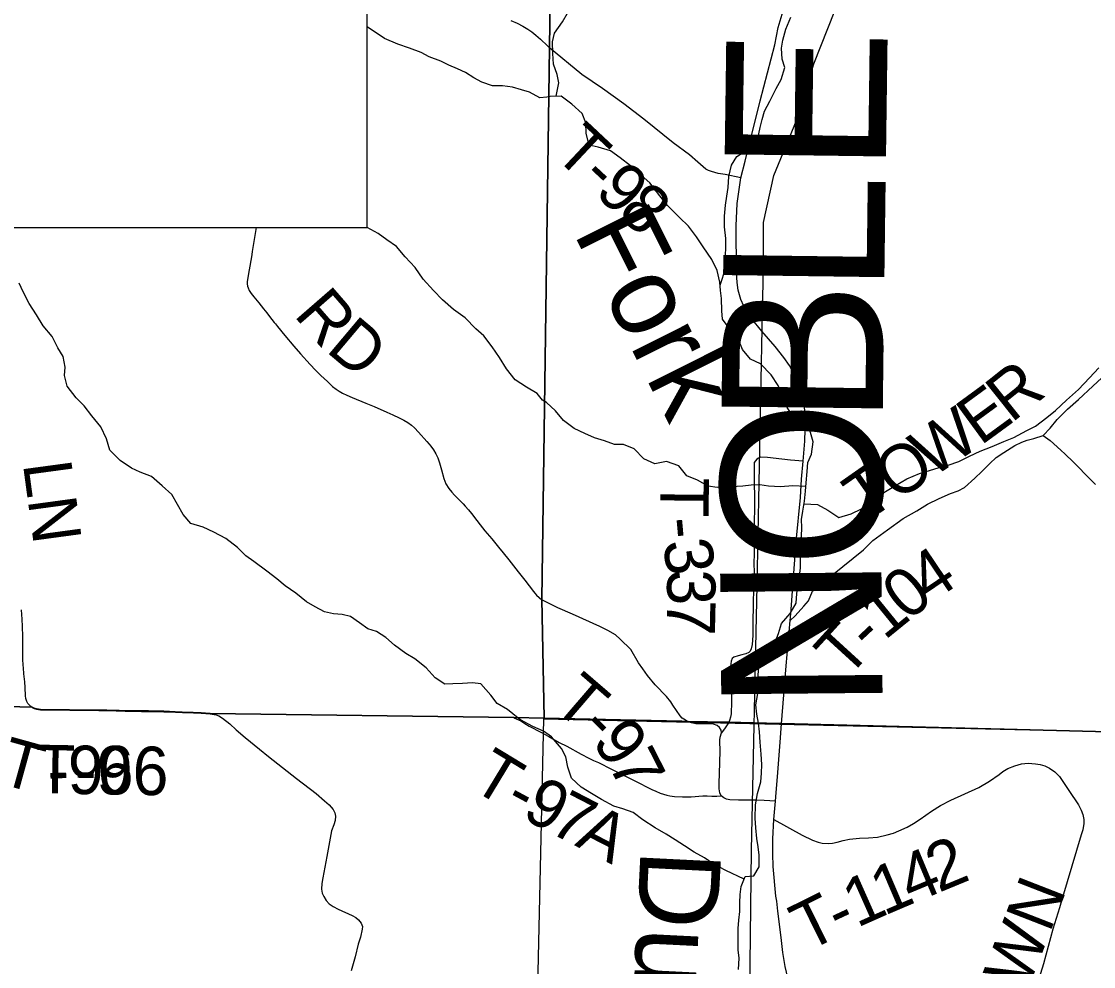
# Model space of a CAD drawing. Extents: x 0 to 34, y 0 to 22.
# Drawn here: x 4.145 to 5.404, y 15.796 to 16.906 of the extents above; entities that cross this region are included whole.
import ezdxf

# ---------------------------------------------------------------- set-up
doc = ezdxf.new("R2010")
doc.units = 0
for name, color, linetype in [('GM_X_Corporation', 7, 'Continuous'), ('GM_X_County_Road', 7, 'Continuous'), ('GM_X_County_Text', 7, 'Continuous'), ('GM_X_Minor_River', 7, 'Continuous'), ('GM_X_Minor_River_Text', 7, 'Continuous'), ('GM_X_Rail_Line', 7, 'Continuous'), ('GM_X_State_Route', 7, 'Continuous'), ('GM_X_Township_Road', 7, 'Continuous'), ('GM_X_Township_Road_Text', 7, 'Continuous'), ('SH_Data', 7, 'Continuous')]:
    doc.layers.add(name, color=color, linetype=linetype)

msp = doc.modelspace()

# ---------------------------------------------------------------- linework, layer by layer
at = {"layer": 'GM_X_Corporation'}
for points in [[(4.7905, 18.3604), (4.7823, 18.128), (4.7806, 18.0273), (4.765, 16.8754), (4.756, 16.2274), (4.759, 16.0879), (4.9206, 16.0842), (4.928, 16.0841), (4.9731, 16.0831), (4.975, 16.083), (5.0347, 16.0817), (5.0373, 16.0816), (6.4668, 16.045), (6.4721, 16.0449), (6.6873, 16.0404), (6.6909, 16.0403), (6.7034, 16.04), (6.9699, 16.0345), (6.9736, 16.0344), (7.8043, 16.0135), (7.8077, 16.0135), (8.4311, 16.0029), (8.4311, 20.028)], [(3.7652, 16.1115), (4.1576, 16.1007), (4.1598, 16.0996), (4.1627, 16.0987), (4.1674, 16.0981), (4.2356, 16.0972), (4.2455, 16.0972), (4.2746, 16.0965), (4.2814, 16.0964), (4.2857, 16.0964), (4.2943, 16.0963), (4.3121, 16.0959), (4.3257, 16.0953), (4.3338, 16.0949), (4.3467, 16.0944), (4.3559, 16.0941), (4.3665, 16.0934), (4.723, 16.0888), (4.759, 16.0879), (4.756, 16.2274), (4.765, 16.8754), (4.7806, 18.0273), (4.7823, 18.128), (4.7905, 18.3604)], [(4.7905, 18.3604), (4.7823, 18.128), (4.7806, 18.0273), (4.765, 16.8754), (4.756, 16.2274), (4.759, 16.0879), (4.723, 16.0888), (4.3665, 16.0934), (4.3559, 16.0941), (4.3467, 16.0944), (4.3338, 16.0949), (4.3257, 16.0953), (4.3121, 16.0959), (4.2943, 16.0963), (4.2857, 16.0964), (4.2814, 16.0964), (4.2746, 16.0965), (4.2455, 16.0972), (4.2356, 16.0972), (4.1674, 16.0981), (4.1627, 16.0987), (4.1598, 16.0996), (4.1576, 16.1007), (3.7652, 16.1115)], [(3.7652, 16.1115), (4.1576, 16.1007), (4.1598, 16.0996), (4.1627, 16.0987), (4.1674, 16.0981), (4.2356, 16.0972), (4.2455, 16.0972), (4.2746, 16.0965), (4.2814, 16.0964), (4.2857, 16.0964), (4.2943, 16.0963), (4.3121, 16.0959), (4.3257, 16.0953), (4.3338, 16.0949), (4.3467, 16.0944), (4.3559, 16.0941), (4.3665, 16.0934), (4.723, 16.0888), (4.759, 16.0879), (4.756, 16.2274), (4.765, 16.8754), (4.7806, 18.0273), (4.7823, 18.128), (4.0508, 18.1454)], [(6.4668, 16.045), (5.0373, 16.0816), (5.0347, 16.0817), (4.975, 16.083), (4.9731, 16.0831), (4.928, 16.0841), (4.9206, 16.0842), (4.759, 16.0879), (4.723, 16.0888), (4.3665, 16.0934), (4.3559, 16.0941), (4.3467, 16.0944), (4.3338, 16.0949), (4.3257, 16.0953), (4.3121, 16.0959), (4.2943, 16.0963), (4.2857, 16.0964), (4.2814, 16.0964), (4.2746, 16.0965), (4.2455, 16.0972), (4.2356, 16.0972), (4.1674, 16.0981), (4.1627, 16.0987), (4.1598, 16.0996), (4.1576, 16.1007), (3.7652, 16.1115)]]:
    msp.add_lwpolyline(points, dxfattribs=at)
msp.add_lwpolyline([(4.7583, 16.0869), (5.7783, 16.0638), (5.82, 16.0635), (5.7937, 15.0184), (4.7356, 15.0283), (4.7361, 15.0901)], close=True, dxfattribs=at)
at = {"layer": 'GM_X_County_Road'}
msp.add_lwpolyline([(4.7198, 16.9071), (4.7271, 16.9036), (4.7337, 16.9002), (4.7396, 16.8967), (4.7442, 16.8936), (4.7491, 16.8898), (4.7546, 16.8848), (4.7627, 16.8771), (4.7652, 16.8748)], dxfattribs=at)
at = {"layer": 'GM_X_Minor_River'}
for points in [[(4.7729, 16.8179), (4.7759, 16.8338), (4.774, 16.8437), (4.7698, 16.8558), (4.769, 16.8683), (4.7686, 16.8819), (4.7708, 16.8922), (4.7802, 16.9055), (4.7863, 16.9157)], [(4.9655, 16.5961), (4.9723, 16.6165), (4.9719, 16.6305), (4.9722, 16.6408), (4.9722, 16.651), (4.9706, 16.6647), (4.9706, 16.6772), (4.9717, 16.6901), (4.9732, 16.7007), (4.975, 16.7109), (4.9758, 16.7238), (4.9788, 16.7371), (4.9852, 16.7473), (4.9991, 16.7561), (5.0097, 16.7683), (5.0123, 16.7812), (5.0149, 16.7907), (5.0176, 16.8005), (5.0236, 16.8123), (5.0311, 16.8271), (5.0371, 16.8377), (5.0413, 16.8518), (5.0382, 16.8616), (5.0374, 16.8745), (5.0389, 16.884), (5.0427, 16.8969), (5.0483, 16.9109)], [(4.7621, 16.8168), (4.7538, 16.816), (4.7416, 16.8228), (4.7321, 16.8257), (4.7215, 16.8287), (4.7097, 16.8301), (4.698, 16.8304), (4.6858, 16.8344), (4.6763, 16.8397), (4.6664, 16.8457), (4.6569, 16.8502), (4.647, 16.8546), (4.6375, 16.8591), (4.6238, 16.8643), (4.6143, 16.8695), (4.6006, 16.8744), (4.5869, 16.8792), (4.5713, 16.8859), (4.5509, 16.8994)], [(4.8728, 16.7253), (4.8602, 16.7363), (4.8481, 16.7457), (4.8367, 16.754), (4.8223, 16.7582), (4.8117, 16.7604), (4.8083, 16.7744), (4.8079, 16.7869), (4.8033, 16.7979), (4.7911, 16.8088), (4.7786, 16.8179), (4.7657, 16.8178), (4.7621, 16.8168)], [(4.9869, 15.7928), (4.9876, 15.8061), (4.9864, 15.8159), (4.9864, 15.8292), (4.9867, 15.8409), (4.9874, 15.8508), (4.9886, 15.861), (4.9885, 15.8709), (4.9889, 15.8808), (4.99, 15.8902), (4.9949, 15.902), (5.0051, 15.9028), (5.0111, 15.9134), (5.0111, 15.9271), (5.0099, 15.9369), (5.0084, 15.9464), (5.0072, 15.9589), (5.0064, 15.9703), (5.0071, 15.9862), (5.0093, 15.9995), (5.0131, 16.0132), (5.0138, 16.0234), (5.0142, 16.0336), (5.0137, 16.0454), (5.0126, 16.0598), (5.0118, 16.0719), (5.0106, 16.0818), (5.0087, 16.0924), (5.0075, 16.1034), (5.0098, 16.1166), (5.0101, 16.1261), (5.0101, 16.1386), (5.0112, 16.1515), (5.0221, 16.1622), (5.0296, 16.1758), (5.0338, 16.1872), (5.0375, 16.199), (5.0477, 16.2108), (5.0545, 16.2229), (5.0556, 16.2343), (5.0578, 16.2495), (5.0597, 16.2639), (5.0596, 16.2783), (5.0573, 16.2893), (5.0611, 16.3011), (5.0614, 16.3117), (5.061, 16.3211), (5.0625, 16.331), (5.0644, 16.3424), (5.0655, 16.3545), (5.0666, 16.364), (5.0677, 16.3773), (5.0684, 16.3879), (5.0725, 16.3978), (5.0748, 16.4122), (5.0706, 16.4258), (5.0633, 16.4379), (5.052, 16.4409), (5.044, 16.4526), (5.039, 16.4644), (5.0337, 16.4784), (5.0253, 16.4908), (5.0128, 16.5037), (5.001, 16.5093), (4.9915, 16.5207), (4.9866, 16.5332), (4.9771, 16.5441), (4.9683, 16.5562), (4.9675, 16.5661), (4.9671, 16.5805), (4.9659, 16.59), (4.9652, 16.5998), (4.9621, 16.6135), (4.9556, 16.6263), (4.9453, 16.6411), (4.9377, 16.6528), (4.9282, 16.6653), (4.9176, 16.6755), (4.9036, 16.6898), (4.8948, 16.7012), (4.883, 16.7163), (4.8728, 16.7253)], [(4.7568, 16.4612), (4.7506, 16.4688), (4.738, 16.4763), (4.7247, 16.4849), (4.7144, 16.4981), (4.7063, 16.5113), (4.6979, 16.5238), (4.6879, 16.5366), (4.6784, 16.5448), (4.6662, 16.5577), (4.6524, 16.5678), (4.6395, 16.5791), (4.6288, 16.59), (4.6166, 16.6032), (4.6074, 16.6171), (4.5955, 16.6296), (4.5856, 16.6416), (4.5741, 16.6495), (4.5639, 16.657), (4.5509, 16.6637)], [(4.7312, 16.0857), (4.7282, 16.088), (4.7159, 16.098), (4.7035, 16.1052), (4.6963, 16.115), (4.6844, 16.1282), (4.6745, 16.1293), (4.6628, 16.1284), (4.6514, 16.128), (4.642, 16.1279), (4.6309, 16.135), (4.6202, 16.1471), (4.6069, 16.1576), (4.5962, 16.1639), (4.5832, 16.1737), (4.5729, 16.1827), (4.5619, 16.1895), (4.5516, 16.1928), (4.5421, 16.1999), (4.5314, 16.2071), (4.5216, 16.2096), (4.5113, 16.2103), (4.5007, 16.2125), (4.49, 16.2185), (4.4798, 16.2245), (4.4672, 16.2346), (4.4546, 16.2433), (4.4451, 16.2515), (4.4333, 16.2605), (4.418, 16.2718), (4.4085, 16.2786), (4.3986, 16.2883), (4.3852, 16.2989), (4.3711, 16.306), (4.3586, 16.3119), (4.3441, 16.3164), (4.335, 16.3269), (4.3284, 16.3386), (4.3215, 16.3503), (4.3101, 16.3605), (4.2979, 16.3714), (4.2846, 16.3766), (4.2743, 16.3815), (4.261, 16.3905), (4.2488, 16.4025), (4.2449, 16.4158), (4.2383, 16.4297), (4.2276, 16.4426), (4.2188, 16.4546), (4.2093, 16.464), (4.1989, 16.4776), (4.1958, 16.4901), (4.1965, 16.5), (4.1941, 16.5125), (4.1876, 16.5227), (4.1811, 16.5359), (4.1704, 16.5484), (4.1627, 16.5612), (4.1543, 16.5748), (4.147, 16.5884), (4.1423, 16.5986)], [(5.0639, 16.3394), (5.0799, 16.3386), (5.092, 16.3319), (5.1049, 16.3236), (5.1193, 16.3278), (5.1314, 16.3335), (5.1431, 16.3389), (5.1556, 16.3514), (5.1715, 16.361), (5.1847, 16.369), (5.1994, 16.3751), (5.2112, 16.3785), (5.2225, 16.382), (5.2331, 16.3847), (5.2456, 16.3893), (5.2584, 16.3954), (5.2709, 16.4011), (5.2849, 16.4068), (5.2985, 16.4126), (5.3102, 16.4175), (5.3254, 16.4256), (5.3356, 16.4305), (5.3492, 16.4408), (5.359, 16.4492), (5.3722, 16.461), (5.3862, 16.4735), (5.399, 16.4872), (5.41, 16.499)], [(5.0661, 16.3598), (5.0507, 16.3605), (5.0363, 16.3593), (5.0223, 16.3601), (5.0121, 16.3619), (5.0018, 16.3615), (4.992, 16.3603), (4.9723, 16.3591), (4.9621, 16.3587), (4.9515, 16.3602), (4.939, 16.3673), (4.9265, 16.3722), (4.917, 16.384), (4.9025, 16.3892), (4.8889, 16.3865), (4.876, 16.3922), (4.8643, 16.4039), (4.8518, 16.4091), (4.8412, 16.4091), (4.8298, 16.4136), (4.818, 16.417), (4.8067, 16.4222), (4.7941, 16.4279), (4.7816, 16.4373), (4.7721, 16.4487), (4.7615, 16.4585), (4.7568, 16.4612)], [(4.9936, 15.8989), (4.9721, 15.9091), (4.9573, 15.9167), (4.9471, 15.9238), (4.935, 15.9306), (4.9236, 15.9378), (4.9126, 15.9449), (4.902, 15.9517), (4.8891, 15.9589), (4.8746, 15.9683), (4.8633, 15.977), (4.8511, 15.9815), (4.8405, 15.9845), (4.8261, 15.9924), (4.8144, 15.9992), (4.8022, 16.0067), (4.7908, 16.0173), (4.7866, 16.0302), (4.7843, 16.0423), (4.779, 16.0522), (4.7676, 16.0658), (4.7581, 16.0726), (4.7456, 16.0782), (4.7312, 16.0857)]]:
    msp.add_lwpolyline(points, dxfattribs=at)
at = {"layer": 'GM_X_Rail_Line'}
msp.add_lwpolyline([(4.997, 15.4988), (5.0024, 15.9327), (5.009, 16.2437), (5.0149, 16.5451), (5.0162, 16.6181), (5.0164, 16.6699), (5.0285, 16.7251), (5.055, 16.7894), (5.0755, 16.8561), (5.1001, 16.9183)], dxfattribs=at)
at = {"layer": 'GM_X_State_Route'}
for points in [[(5.032, 16.0094), (5.0333, 16.024), (5.0358, 16.0595), (5.0375, 16.081), (5.0431, 16.1491), (5.0478, 16.2025), (5.0483, 16.2103), (5.0548, 16.2954), (5.0596, 16.347), (5.0611, 16.3684), (5.0628, 16.3896), (5.0647, 16.4129), (5.0655, 16.4408), (5.0647, 16.4498), (5.0634, 16.4588), (5.0623, 16.4654), (5.06, 16.4729), (5.057, 16.4812), (5.0527, 16.4904), (5.0469, 16.5017), (5.0403, 16.5113), (5.03, 16.5241), (5.0144, 16.5421), (5.0023, 16.5572), (4.9933, 16.5714), (4.9896, 16.5794), (4.9864, 16.5905), (4.9853, 16.5992), (4.9848, 16.6115), (4.9841, 16.666), (4.9855, 16.6921), (4.9899, 16.7223), (4.9948, 16.7416), (5.0124, 16.8127), (5.0295, 16.8784), (5.0337, 16.8985), (5.0405, 16.9223)], [(5.0306, 15.9903), (5.0313, 16.0007), (5.032, 16.0094)], [(5.0467, 15.7749), (5.0418, 15.7963), (5.0392, 15.8129), (5.0369, 15.8305), (5.0332, 15.8613), (5.0318, 15.8728), (5.0308, 15.8788), (5.0277, 15.9138), (5.0273, 15.9287), (5.0272, 15.9462), (5.0285, 15.9688), (5.0306, 15.9903)]]:
    msp.add_lwpolyline(points, dxfattribs=at)
at = {"layer": 'GM_X_Township_Road'}
for points in [[(4.9899, 16.7223), (4.9712, 16.7261), (4.9633, 16.7274), (4.9554, 16.7295), (4.9518, 16.7307), (4.9488, 16.7325), (4.9392, 16.7405), (4.9294, 16.7491), (4.9103, 16.7634), (4.8758, 16.791), (4.8523, 16.8091), (4.8273, 16.8271), (4.8029, 16.8437), (4.7652, 16.8748)], [(4.4206, 16.6637), (4.416, 16.6356), (4.4154, 16.632), (4.4151, 16.6295), (4.4124, 16.6142), (4.4107, 16.6051), (4.4101, 16.6001), (4.4101, 16.5976), (4.4105, 16.5952), (4.4112, 16.5929), (4.4125, 16.5901), (4.4149, 16.5865), (4.418, 16.5826), (4.4238, 16.5753), (4.4292, 16.5685), (4.433, 16.5636), (4.4376, 16.5578), (4.4392, 16.5559), (4.4419, 16.5525), (4.4435, 16.5506), (4.4458, 16.5477), (4.4545, 16.5372), (4.4647, 16.5247), (4.4729, 16.5154), (4.4841, 16.503), (4.4905, 16.4963), (4.4967, 16.4902), (4.5043, 16.4829), (4.5102, 16.4774), (4.5146, 16.474), (4.5182, 16.4716), (4.522, 16.4695), (4.527, 16.467), (4.5333, 16.4643), (4.5493, 16.4577), (4.5591, 16.4536), (4.5739, 16.4471), (4.5813, 16.4439), (4.5887, 16.4406), (4.5941, 16.4377), (4.5989, 16.4348), (4.6029, 16.4318), (4.6066, 16.4285), (4.6114, 16.4237), (4.6212, 16.4125), (4.6238, 16.4095)], [(5.0478, 16.2025), (5.0535, 16.208), (5.0637, 16.2195), (5.0692, 16.2255), (5.074, 16.2369), (5.0838, 16.2449), (5.0973, 16.256), (5.1338, 16.2855), (5.1447, 16.2964), (5.1618, 16.309), (5.1805, 16.3221), (5.1963, 16.3312), (5.2087, 16.3389), (5.2224, 16.3457), (5.236, 16.3514), (5.2449, 16.3549), (5.2522, 16.3588), (5.2643, 16.3694), (5.2728, 16.3776), (5.2819, 16.3868), (5.2896, 16.3937), (5.2986, 16.3998), (5.3113, 16.408), (5.3195, 16.4118), (5.3261, 16.4144), (5.3336, 16.4163), (5.3447, 16.4198), (5.3528, 16.4282), (5.3612, 16.4385), (5.3732, 16.4505), (5.386, 16.4621), (5.403, 16.4776), (5.4185, 16.4922)], [(5.3447, 16.4198), (5.3531, 16.4139), (5.3656, 16.4025), (5.3704, 16.3978), (5.38, 16.3889), (5.3858, 16.3829), (5.3951, 16.3733), (5.4063, 16.3621)], [(4.6238, 16.4095), (4.6256, 16.4073), (4.6289, 16.4028), (4.6318, 16.398), (4.6338, 16.3935), (4.6359, 16.3877), (4.6382, 16.3793), (4.641, 16.3692), (4.6435, 16.3629), (4.6467, 16.3576), (4.6502, 16.3532), (4.6537, 16.3496), (4.6607, 16.3426), (4.6624, 16.3408), (4.6636, 16.3394), (4.6661, 16.3366), (4.6698, 16.3324), (4.6733, 16.3281), (4.6798, 16.3197), (4.6835, 16.3148), (4.6893, 16.3076), (4.6973, 16.2982), (4.7051, 16.2886), (4.7106, 16.2819), (4.7172, 16.2737), (4.7283, 16.2595), (4.736, 16.25), (4.7461, 16.2367), (4.7478, 16.2347), (4.75, 16.2321), (4.7529, 16.2294), (4.7562, 16.2269)], [(5.0628, 16.3896), (5.0479, 16.3908), (5.038, 16.3918), (5.0211, 16.3938), (5.0129, 16.3942), (5.0104, 16.393), (5.0086, 16.3918), (5.007, 16.3901), (5.0054, 16.3878), (5.0054, 16.3667), (5.0058, 16.3444), (5.0057, 16.3303), (5.0055, 16.3218), (5.0052, 16.2934), (5.0052, 16.2821), (5.005, 16.2686), (5.0053, 16.2602), (5.005, 16.2515), (5.0046, 16.2409), (5.0041, 16.2213), (5.0038, 16.1996), (5.0037, 16.1848), (5.0031, 16.1743), (5.002, 16.1692), (5.0007, 16.1663), (4.9992, 16.1649), (4.9954, 16.1633), (4.991, 16.162), (4.9865, 16.1611), (4.9815, 16.1596), (4.9795, 16.1578), (4.9784, 16.1547), (4.978, 16.1517), (4.9787, 16.1397), (4.9786, 16.1139), (4.9786, 16.1034), (4.9784, 16.0963), (4.9782, 16.0929), (4.9775, 16.089), (4.9763, 16.085), (4.9752, 16.0825), (4.9715, 16.0766), (4.9669, 16.0706)], [(4.9246, 16.0855), (4.9208, 16.0879), (4.9185, 16.0905), (4.9098, 16.1032), (4.9074, 16.1069), (4.9023, 16.1133), (4.8892, 16.127), (4.8801, 16.1379), (4.8745, 16.1458), (4.8697, 16.1528), (4.8605, 16.1683), (4.8482, 16.1804), (4.8424, 16.1856), (4.8337, 16.1909), (4.8243, 16.1955), (4.7922, 16.2098), (4.7747, 16.2174), (4.7562, 16.2269)], [(4.1578, 16.1002), (4.1561, 16.1015), (4.1545, 16.1029), (4.1527, 16.105), (4.1514, 16.1074), (4.1504, 16.1109), (4.15, 16.1139), (4.1496, 16.1237), (4.1491, 16.1304), (4.148, 16.1397), (4.1473, 16.1471), (4.147, 16.1501), (4.1467, 16.1569), (4.1465, 16.1644), (4.1466, 16.1706), (4.1467, 16.1805), (4.1467, 16.1836), (4.1462, 16.1954), (4.1458, 16.204), (4.145, 16.2151)], [(4.1578, 16.1002), (4.16, 16.0991), (4.1629, 16.0982), (4.1676, 16.0976), (4.2358, 16.0967), (4.2457, 16.0967), (4.2668, 16.0961), (4.2748, 16.096), (4.2816, 16.0959), (4.2859, 16.0958), (4.2945, 16.0958), (4.3123, 16.0953), (4.326, 16.0947), (4.334, 16.0944), (4.3469, 16.0939), (4.3562, 16.0935), (4.3667, 16.0929)], [(4.3667, 16.0929), (4.3737, 16.0916), (4.3769, 16.0905), (4.3812, 16.088), (4.3897, 16.081), (4.3972, 16.0742), (4.4077, 16.0651), (4.4244, 16.0514), (4.4352, 16.0429), (4.4681, 16.0168), (4.4911, 15.9992), (4.501, 15.9909), (4.5065, 15.986), (4.5109, 15.9807), (4.5131, 15.9766), (4.5138, 15.9726), (4.5136, 15.9677), (4.5119, 15.9624), (4.5092, 15.9555), (4.5035, 15.9256), (4.4988, 15.9005), (4.4977, 15.8936), (4.4973, 15.8872), (4.4983, 15.8825), (4.5, 15.8784), (4.503, 15.8738), (4.5064, 15.87), (4.5109, 15.8667), (4.5168, 15.8636), (4.5334, 15.8561), (4.5375, 15.8538), (4.541, 15.8509), (4.5438, 15.8471), (4.5454, 15.8431), (4.5452, 15.84), (4.5431, 15.8308), (4.5406, 15.8225), (4.5367, 15.8078), (4.5323, 15.7913)], [(4.7232, 16.0882), (4.7313, 16.0845), (4.7361, 16.0814), (4.7412, 16.0786), (4.755, 16.0714), (4.7643, 16.0663), (4.7763, 16.0592), (4.7854, 16.0548), (4.8021, 16.0454), (4.8113, 16.0407), (4.8169, 16.038), (4.8225, 16.0357), (4.8379, 16.0281), (4.8607, 16.0166), (4.8709, 16.0117), (4.8798, 16.007), (4.8852, 16.0042), (4.8899, 16.0021), (4.8949, 15.9999), (4.8988, 15.9985), (4.9027, 15.9974), (4.9064, 15.9967), (4.909, 15.9962), (4.9117, 15.9959), (4.9213, 15.9955), (4.9316, 15.9954), (4.9451, 15.9967), (4.95, 15.9968), (4.9555, 15.9964), (4.9615, 15.9963), (4.9667, 15.9965)], [(4.9669, 16.0706), (4.9665, 16.0738), (4.9648, 16.0768), (4.9619, 16.0794), (4.9577, 16.0808), (4.9536, 16.0812), (4.9367, 16.0813), (4.9319, 16.0824), (4.9282, 16.0835), (4.9246, 16.0855)], [(5.0306, 15.9903), (5.0172, 15.9911), (5.0075, 15.9916), (4.9974, 15.9917), (4.9868, 15.9915), (4.9767, 15.992), (4.9727, 15.9929), (4.9697, 15.9943), (4.9667, 15.9965), (4.965, 16.0001), (4.9643, 16.005), (4.9643, 16.0127), (4.9646, 16.0217), (4.965, 16.037), (4.9653, 16.0483), (4.9652, 16.062), (4.9655, 16.0655), (4.9669, 16.0706)], [(5.0285, 15.9688), (5.0619, 15.9503), (5.0737, 15.9445), (5.0804, 15.9422), (5.0854, 15.941), (5.0927, 15.9405), (5.0975, 15.941), (5.1029, 15.9422), (5.1098, 15.9442), (5.1174, 15.9456), (5.1289, 15.947), (5.1397, 15.9475), (5.15, 15.9482), (5.1617, 15.9507), (5.1688, 15.953), (5.1753, 15.9554), (5.1849, 15.9599), (5.1926, 15.9641), (5.2003, 15.9694), (5.2135, 15.9785), (5.2243, 15.9851), (5.2364, 15.9914), (5.2691, 16.0063), (5.2816, 16.014), (5.2931, 16.0218), (5.2975, 16.0253), (5.3034, 16.0289), (5.3113, 16.0319), (5.3194, 16.0343), (5.3271, 16.0348), (5.3357, 16.0344), (5.3411, 16.0335), (5.3466, 16.0319), (5.3523, 16.0292), (5.3583, 16.0247), (5.3637, 16.0192), (5.375, 16.003), (5.3861, 15.9861), (5.3892, 15.98), (5.3912, 15.9748), (5.3926, 15.9688), (5.3925, 15.9642), (5.3911, 15.9569), (5.3895, 15.9509), (5.3785, 15.9141), (5.3673, 15.8774), (5.3637, 15.8651), (5.3561, 15.8402), (5.345, 15.7995), (5.3396, 15.7819)]]:
    msp.add_lwpolyline(points, dxfattribs=at)
at = {"layer": 'SH_Data'}
msp.add_lwpolyline([(1.8974, 16.6637), (4.5509, 16.6637), (4.5509, 17.3579), (1.8974, 17.3579)], close=True, dxfattribs=at)

# ---------------------------------------------------------------- texts
at = {"layer": 'GM_X_County_Text'}
for s, rotation, p in [('E', 89.2311, (5.1599, 16.7265)), ('L', 89.2485, (5.158, 16.5848)), ('B', 89.3168, (5.1562, 16.4307)), ('O', 89.5387, (5.1548, 16.2634)), ('N', 90.5179, (5.1563, 16.0968))]:
    msp.add_text(s, height=0.1894, rotation=rotation, dxfattribs=at).set_placement(p)
at = {"layer": 'GM_X_Minor_River_Text'}
for s, height, rotation, p in [('Fork', 0.09469, 296.6104, (4.7924, 16.6583)), ('Duck', 0.0947, 267.1501, (4.8721, 15.9346))]:
    msp.add_text(s, height=height, rotation=rotation, dxfattribs=at).set_placement(p)
at = {"layer": 'GM_X_Township_Road_Text'}
for s, height, rotation, p in [('T', 0.0568, 316.8003, (4.7682, 16.7492)), ('-', 0.0568, 316.877, (4.7993, 16.7201)), ('9', 0.0568, 317.2092, (4.8166, 16.7039)), ('8', 0.0568, 318.6621, (4.8434, 16.6791)), ('R', 0.0568, 311.0158, (4.4638, 16.561)), ('D', 0.0568, 319.901, (4.5012, 16.5192)), ('R', 0.0568, 38.5467, (5.3073, 16.4336)), ('E', 0.0568, 36.1723, (5.271, 16.407)), ('W', 0.0568, 33.4408, (5.2136, 16.369)), ('O', 0.0568, 33.1909, (5.1715, 16.3415)), ('LN', 0.05682, 277.7028, (4.1467, 16.3864)), ('T', 0.0568, 34.9941, (5.1371, 16.3174)), ('T', 0.0568, 269.5586, (4.8955, 16.3702)), ('-', 0.0568, 275.0908, (4.8954, 16.3218)), ('3', 0.0568, 278.5086, (4.8979, 16.2948)), ('4', 0.0568, 33.9888, (5.2117, 16.2218)), ('0', 0.0568, 38.9321, (5.1855, 16.2006)), ('3', 0.0568, 270.6974, (4.9029, 16.2623)), ('1', 0.0568, 39.0759, (5.1584, 16.1785)), ('7', 0.0568, 268.6989, (4.9034, 16.2278)), ('T', 0.0568, 47.607, (5.1143, 16.1327)), ('-', 0.0568, 43.1396, (5.1421, 16.1633)), ('T', 0.0568, 319.3043, (4.7671, 16.1016)), ('-', 0.0568, 314.6909, (4.7985, 16.0747)), ('9', 0.0568, 307.2269, (4.8136, 16.0596)), ('T', 0.0568, 344.5147, (4.1169, 16.0117)), ('T-96', 0.05682, 358.9575, (4.1611, 16)), ('9', 0.0568, 359.4197, (4.1991, 15.9989)), ('6', 0.0568, 359.5854, (4.2343, 15.9986)), ('T', 0.0568, 328.7628, (4.6708, 16.0064)), ('7', 0.0568, 297.091, (4.8333, 16.034)), ('-', 0.0568, 1.9734, (4.1765, 15.9981)), ('9', 0.0568, 332.2211, (4.7309, 15.9715)), ('-', 0.0568, 331.7007, (4.7099, 15.9828)), ('7', 0.0568, 332.6839, (4.7623, 15.9549)), ('A', 0.0568, 332.8402, (4.7936, 15.9388)), ('2', 0.0568, 22.4633, (5.2221, 15.8827)), ('4', 0.0568, 22.6103, (5.1898, 15.8692)), ('1', 0.0568, 23.1186, (5.1577, 15.8555)), ('1', 0.0568, 23.9878, (5.126, 15.8414)), ('BROWN', 0.05682, 68.739, (5.2667, 15.6144)), ('T', 0.0568, 26.3312, (5.0673, 15.8129)), ('-', 0.0568, 25.1197, (5.1051, 15.8316))]:
    msp.add_text(s, height=height, rotation=rotation, dxfattribs=at).set_placement(p)

doc.saveas('drawing.dxf')
